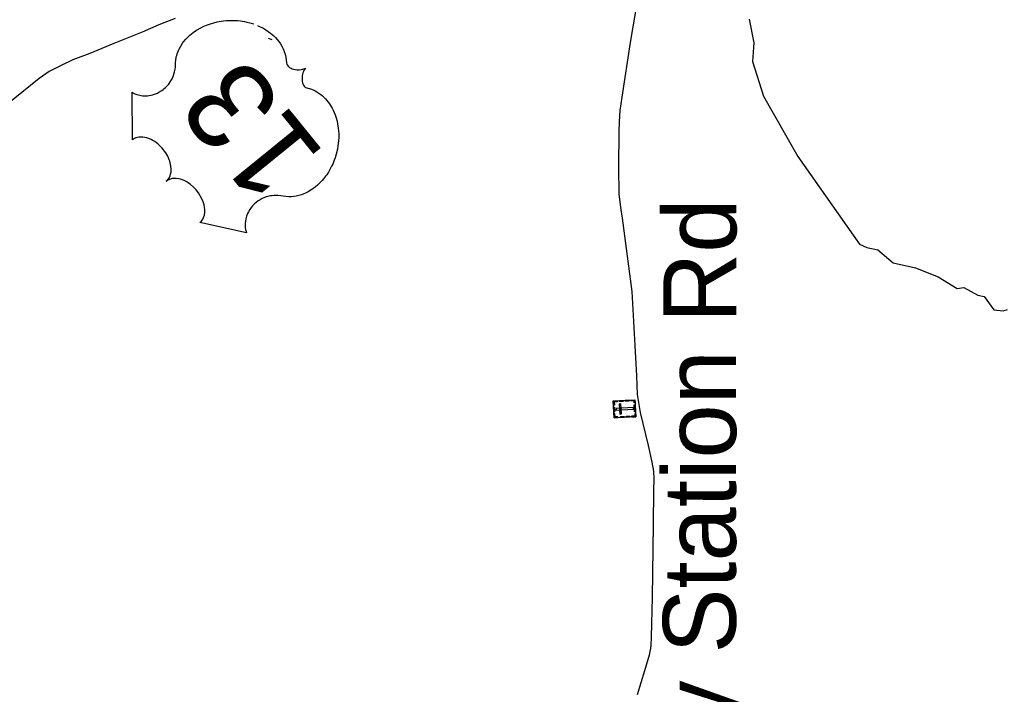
# Model space of a CAD drawing. Extents: x 2596159 to 2598075, y 851667 to 853493.
# Drawn here: x 2597062 to 2597143.5, y 851821.9 to 851877.7 of the extents above; entities that cross this region are included whole.
import ezdxf

# ---------------------------------------------------------------- set-up
doc = ezdxf.new("R2010")
doc.units = 0
doc.layers.add('Old_Level_1', color=7, linetype='Continuous')

msp = doc.modelspace()

# ---------------------------------------------------------------- linework, layer by layer
at = {"layer": 'Old_Level_1'}
for p, q in [((2597113.161, 851879.683), (2597112.506, 851875.786)), ((2597074.892, 851877.79), (2597073.528, 851877.271)), ((2597077.71, 851877.321), (2597078.071, 851877.433)), ((2597078.071, 851877.433), (2597078.348, 851877.497)), ((2597078.348, 851877.497), (2597078.682, 851877.56)), ((2597078.682, 851877.56), (2597078.892, 851877.588)), ((2597078.892, 851877.588), (2597079.123, 851877.609)), ((2597079.123, 851877.609), (2597079.397, 851877.623)), ((2597079.397, 851877.623), (2597079.7, 851877.626)), ((2597079.7, 851877.626), (2597080.038, 851877.607)), ((2597080.038, 851877.607), (2597080.296, 851877.58)), ((2597080.296, 851877.58), (2597080.614, 851877.529)), ((2597080.614, 851877.529), (2597080.799, 851877.492)), ((2597080.799, 851877.492), (2597081.052, 851877.43)), ((2597081.052, 851877.43), (2597081.378, 851877.329)), ((2597122.358, 851877.74), (2597122.735, 851875.782)), ((2597072.159, 851876.651), (2597069.818, 851875.72)), ((2597073.528, 851877.271), (2597072.159, 851876.651)), ((2597076.091, 851876.395), (2597076.367, 851876.62)), ((2597076.367, 851876.62), (2597076.647, 851876.813)), ((2597076.647, 851876.813), (2597076.994, 851877.013)), ((2597076.994, 851877.013), (2597077.211, 851877.121)), ((2597077.211, 851877.121), (2597077.475, 851877.231)), ((2597077.475, 851877.231), (2597077.71, 851877.321)), ((2597081.68, 851877.214), (2597081.925, 851877.106)), ((2597081.925, 851877.106), (2597082.129, 851876.999)), ((2597082.129, 851876.999), (2597082.382, 851876.853)), ((2597082.382, 851876.853), (2597082.766, 851876.579)), ((2597075.495, 851875.731), (2597075.577, 851875.844)), ((2597075.577, 851875.844), (2597075.775, 851876.079)), ((2597075.775, 851876.079), (2597075.877, 851876.19)), ((2597075.877, 851876.19), (2597076.091, 851876.395)), ((2597082.579, 851876.169), (2597082.881, 851876.053)), ((2597082.766, 851876.579), (2597082.897, 851876.472)), ((2597082.897, 851876.472), (2597083.044, 851876.338)), ((2597083.044, 851876.338), (2597083.174, 851876.207)), ((2597083.174, 851876.207), (2597083.295, 851876.076)), ((2597083.295, 851876.076), (2597083.446, 851875.889)), ((2597083.446, 851875.889), (2597083.583, 851875.693)), ((2597069.818, 851875.72), (2597067.831, 851874.886)), ((2597075.052, 851874.867), (2597075.101, 851875)), ((2597075.101, 851875), (2597075.157, 851875.139)), ((2597075.157, 851875.139), (2597075.209, 851875.257)), ((2597075.209, 851875.257), (2597075.346, 851875.507)), ((2597075.346, 851875.507), (2597075.495, 851875.731)), ((2597083.583, 851875.693), (2597083.7, 851875.497)), ((2597083.7, 851875.497), (2597083.809, 851875.284)), ((2597083.809, 851875.284), (2597083.908, 851875.047)), ((2597083.908, 851875.047), (2597083.981, 851874.819)), ((2597112.506, 851875.786), (2597111.828, 851871.278)), ((2597122.735, 851875.782), (2597122.635, 851874.218)), ((2597066.412, 851874.357), (2597065.464, 851873.898)), ((2597067.831, 851874.886), (2597066.412, 851874.357)), ((2597074.908, 851874.146), (2597074.926, 851874.312)), ((2597074.926, 851874.312), (2597074.978, 851874.603)), ((2597074.978, 851874.603), (2597075.01, 851874.731)), ((2597075.01, 851874.731), (2597075.052, 851874.867)), ((2597083.981, 851874.819), (2597084.037, 851874.574)), ((2597084.037, 851874.574), (2597084.091, 851874.126)), ((2597122.635, 851874.218), (2597123.527, 851871.357)), ((2597064.471, 851873.392), (2597063.636, 851872.809)), ((2597065.464, 851873.898), (2597064.471, 851873.392)), ((2597074.742, 851873.069), (2597074.84, 851873.382)), ((2597074.84, 851873.382), (2597074.877, 851873.579)), ((2597074.877, 851873.579), (2597074.898, 851873.76)), ((2597074.898, 851873.76), (2597074.903, 851874.009)), ((2597074.903, 851874.009), (2597074.908, 851874.146)), ((2597084.091, 851874.126), (2597084.115, 851874.004)), ((2597084.115, 851874.004), (2597084.141, 851873.946)), ((2597084.141, 851873.946), (2597084.229, 851873.827)), ((2597084.229, 851873.827), (2597084.338, 851873.738)), ((2597084.338, 851873.738), (2597084.472, 851873.663)), ((2597084.472, 851873.663), (2597084.561, 851873.626)), ((2597084.561, 851873.626), (2597084.691, 851873.585)), ((2597084.691, 851873.585), (2597084.8, 851873.56)), ((2597084.8, 851873.56), (2597084.944, 851873.542)), ((2597084.944, 851873.542), (2597085.055, 851873.538)), ((2597085.055, 851873.538), (2597085.141, 851873.536)), ((2597085.141, 851873.536), (2597085.34, 851873.56)), ((2597085.34, 851873.56), (2597085.426, 851873.581)), ((2597085.426, 851873.581), (2597085.532, 851873.615)), ((2597085.49, 851873.401), (2597085.447, 851873.281)), ((2597085.553, 851873.525), (2597085.49, 851873.401)), ((2597085.532, 851873.615), (2597085.672, 851873.684)), ((2597085.672, 851873.684), (2597085.553, 851873.525)), ((2597063.636, 851872.809), (2597057.987, 851868.27)), ((2597074.439, 851872.484), (2597074.537, 851872.634)), ((2597074.537, 851872.634), (2597074.623, 851872.791)), ((2597074.623, 851872.791), (2597074.742, 851873.069)), ((2597085.386, 851873.006), (2597085.375, 851872.872)), ((2597085.375, 851872.872), (2597085.375, 851872.722)), ((2597085.375, 851872.722), (2597085.395, 851872.579)), ((2597085.415, 851873.167), (2597085.386, 851873.006)), ((2597085.395, 851872.579), (2597085.418, 851872.47)), ((2597085.447, 851873.281), (2597085.415, 851873.167)), ((2597073.539, 851871.677), (2597073.775, 851871.823)), ((2597073.775, 851871.823), (2597073.882, 851871.898)), ((2597073.882, 851871.898), (2597073.983, 851871.98)), ((2597073.983, 851871.98), (2597074.084, 851872.071)), ((2597074.084, 851872.071), (2597074.178, 851872.164)), ((2597074.178, 851872.164), (2597074.269, 851872.268)), ((2597074.269, 851872.268), (2597074.348, 851872.361)), ((2597074.348, 851872.361), (2597074.439, 851872.484)), ((2597085.418, 851872.47), (2597085.449, 851872.378)), ((2597085.449, 851872.378), (2597085.498, 851872.274)), ((2597085.498, 851872.274), (2597085.549, 851872.199)), ((2597085.549, 851872.199), (2597085.598, 851872.142)), ((2597085.598, 851872.142), (2597085.681, 851872.077)), ((2597085.681, 851872.077), (2597085.847, 851872.033)), ((2597085.847, 851872.033), (2597086, 851871.988)), ((2597086, 851871.988), (2597086.16, 851871.932)), ((2597086.16, 851871.932), (2597086.339, 851871.857)), ((2597086.339, 851871.857), (2597086.463, 851871.796)), ((2597086.463, 851871.796), (2597086.603, 851871.717)), ((2597086.603, 851871.717), (2597086.758, 851871.618)), ((2597071.36, 851867.738), (2597071.321, 851871.677)), ((2597071.321, 851871.677), (2597071.389, 851871.638)), ((2597071.389, 851871.638), (2597071.558, 851871.56)), ((2597071.558, 851871.56), (2597071.702, 851871.506)), ((2597071.702, 851871.506), (2597071.952, 851871.436)), ((2597071.952, 851871.436), (2597072.073, 851871.417)), ((2597072.073, 851871.417), (2597072.197, 851871.4)), ((2597072.197, 851871.4), (2597072.32, 851871.393)), ((2597072.32, 851871.393), (2597072.433, 851871.39)), ((2597072.433, 851871.39), (2597072.585, 851871.398)), ((2597072.585, 851871.398), (2597072.732, 851871.414)), ((2597072.732, 851871.414), (2597072.887, 851871.44)), ((2597072.887, 851871.44), (2597073.015, 851871.47)), ((2597073.015, 851871.47), (2597073.267, 851871.553)), ((2597073.267, 851871.553), (2597073.417, 851871.616)), ((2597073.417, 851871.616), (2597073.539, 851871.677)), ((2597086.758, 851871.618), (2597086.916, 851871.503)), ((2597086.916, 851871.503), (2597087.068, 851871.376)), ((2597087.068, 851871.376), (2597087.197, 851871.26)), ((2597087.197, 851871.26), (2597087.326, 851871.128)), ((2597087.326, 851871.128), (2597087.434, 851871.003)), ((2597087.434, 851871.003), (2597087.542, 851870.867)), ((2597111.828, 851871.278), (2597111.662, 851870.173)), ((2597123.527, 851871.357), (2597126.377, 851866.381)), ((2597087.542, 851870.867), (2597087.634, 851870.734)), ((2597087.634, 851870.734), (2597087.74, 851870.578)), ((2597087.74, 851870.578), (2597087.86, 851870.375)), ((2597087.86, 851870.375), (2597087.948, 851870.198)), ((2597087.948, 851870.198), (2597088.034, 851870.006)), ((2597111.662, 851870.173), (2597111.591, 851869.24)), ((2597088.034, 851870.006), (2597088.115, 851869.802)), ((2597088.115, 851869.802), (2597088.19, 851869.574)), ((2597088.19, 851869.574), (2597088.272, 851869.28)), ((2597088.272, 851869.28), (2597088.317, 851869.065)), ((2597088.317, 851869.065), (2597088.374, 851868.715)), ((2597088.374, 851868.715), (2597088.407, 851868.279)), ((2597111.591, 851869.24), (2597111.576, 851868.429)), ((2597071.433, 851867.793), (2597071.36, 851867.738)), ((2597071.525, 851867.85), (2597071.433, 851867.793)), ((2597071.64, 851867.905), (2597071.525, 851867.85)), ((2597071.762, 851867.94), (2597071.64, 851867.905)), ((2597071.881, 851867.969), (2597071.762, 851867.94)), ((2597072.012, 851867.979), (2597071.881, 851867.969)), ((2597072.206, 851867.973), (2597072.012, 851867.979)), ((2597072.387, 851867.947), (2597072.206, 851867.973)), ((2597072.529, 851867.917), (2597072.387, 851867.947)), ((2597072.702, 851867.857), (2597072.529, 851867.917)), ((2597072.9, 851867.772), (2597072.702, 851867.857)), ((2597073.042, 851867.698), (2597072.9, 851867.772)), ((2597073.195, 851867.606), (2597073.042, 851867.698)), ((2597088.394, 851867.66), (2597088.347, 851867.244)), ((2597088.408, 851867.928), (2597088.394, 851867.66)), ((2597088.407, 851868.279), (2597088.408, 851867.928)), ((2597111.576, 851868.429), (2597111.555, 851865.48)), ((2597073.35, 851867.493), (2597073.195, 851867.606)), ((2597073.462, 851867.404), (2597073.35, 851867.493)), ((2597073.595, 851867.287), (2597073.462, 851867.404)), ((2597073.709, 851867.175), (2597073.595, 851867.287)), ((2597073.814, 851867.061), (2597073.709, 851867.175)), ((2597073.921, 851866.932), (2597073.814, 851867.061)), ((2597074.004, 851866.824), (2597073.921, 851866.932)), ((2597088.304, 851866.988), (2597088.203, 851866.558)), ((2597088.347, 851867.244), (2597088.304, 851866.988)), ((2597074.1, 851866.686), (2597074.004, 851866.824)), ((2597074.185, 851866.544), (2597074.1, 851866.686)), ((2597074.264, 851866.402), (2597074.185, 851866.544)), ((2597074.337, 851866.253), (2597074.264, 851866.402)), ((2597074.399, 851866.101), (2597074.337, 851866.253)), ((2597074.443, 851865.978), (2597074.399, 851866.101)), ((2597088.042, 851866.06), (2597087.914, 851865.745)), ((2597088.116, 851866.264), (2597088.042, 851866.06)), ((2597088.203, 851866.558), (2597088.116, 851866.264)), ((2597126.377, 851866.381), (2597131.469, 851859.124)), ((2597074.478, 851865.851), (2597074.443, 851865.978)), ((2597074.536, 851865.583), (2597074.478, 851865.851)), ((2597074.556, 851865.33), (2597074.536, 851865.583)), ((2597074.548, 851865.112), (2597074.556, 851865.229)), ((2597074.556, 851865.229), (2597074.556, 851865.33)), ((2597087.687, 851865.294), (2597087.551, 851865.065)), ((2597087.825, 851865.557), (2597087.687, 851865.294)), ((2597087.914, 851865.745), (2597087.825, 851865.557)), ((2597111.555, 851865.48), (2597111.585, 851863.281)), ((2597074.143, 851864.318), (2597074.248, 851864.417)), ((2597074.284, 851864.416), (2597074.143, 851864.318)), ((2597074.248, 851864.417), (2597074.308, 851864.484)), ((2597074.359, 851864.453), (2597074.284, 851864.416)), ((2597074.308, 851864.484), (2597074.361, 851864.558)), ((2597074.544, 851864.52), (2597074.359, 851864.453)), ((2597074.361, 851864.558), (2597074.41, 851864.645)), ((2597074.41, 851864.645), (2597074.47, 851864.778)), ((2597074.47, 851864.778), (2597074.509, 851864.904)), ((2597074.509, 851864.904), (2597074.548, 851865.112)), ((2597074.641, 851864.539), (2597074.544, 851864.52)), ((2597074.746, 851864.554), (2597074.641, 851864.539)), ((2597074.954, 851864.555), (2597074.746, 851864.554)), ((2597075.179, 851864.527), (2597074.954, 851864.555)), ((2597075.317, 851864.49), (2597075.179, 851864.527)), ((2597075.483, 851864.435), (2597075.317, 851864.49)), ((2597075.676, 851864.354), (2597075.483, 851864.435)), ((2597087.156, 851864.518), (2597087.033, 851864.372)), ((2597087.324, 851864.73), (2597087.156, 851864.518)), ((2597087.416, 851864.857), (2597087.324, 851864.73)), ((2597087.551, 851865.065), (2597087.416, 851864.857)), ((2597075.835, 851864.268), (2597075.676, 851864.354)), ((2597075.996, 851864.167), (2597075.835, 851864.268)), ((2597076.131, 851864.068), (2597075.996, 851864.167)), ((2597076.404, 851863.839), (2597076.131, 851864.068)), ((2597076.622, 851863.609), (2597076.404, 851863.839)), ((2597076.802, 851863.378), (2597076.622, 851863.609)), ((2597086.098, 851863.577), (2597085.873, 851863.447)), ((2597086.301, 851863.711), (2597086.098, 851863.577)), ((2597086.466, 851863.837), (2597086.301, 851863.711)), ((2597086.657, 851863.998), (2597086.466, 851863.837)), ((2597086.856, 851864.183), (2597086.657, 851863.998)), ((2597087.033, 851864.372), (2597086.856, 851864.183)), ((2597076.964, 851863.127), (2597076.802, 851863.378)), ((2597077.093, 851862.882), (2597076.964, 851863.127)), ((2597077.201, 851862.628), (2597077.093, 851862.882)), ((2597081.909, 851862.796), (2597081.757, 851862.703)), ((2597082.078, 851862.886), (2597081.909, 851862.796)), ((2597082.213, 851862.95), (2597082.078, 851862.886)), ((2597082.419, 851863.026), (2597082.213, 851862.95)), ((2597082.559, 851863.067), (2597082.419, 851863.026)), ((2597082.758, 851863.108), (2597082.559, 851863.067)), ((2597082.898, 851863.13), (2597082.758, 851863.108)), ((2597083.06, 851863.147), (2597082.898, 851863.13)), ((2597083.245, 851863.153), (2597083.06, 851863.147)), ((2597083.385, 851863.148), (2597083.245, 851863.153)), ((2597083.633, 851863.119), (2597083.385, 851863.148)), ((2597083.823, 851863.08), (2597083.633, 851863.119)), ((2597084.048, 851863.052), (2597083.823, 851863.08)), ((2597084.28, 851863.037), (2597084.048, 851863.052)), ((2597084.476, 851863.042), (2597084.28, 851863.037)), ((2597084.694, 851863.062), (2597084.476, 851863.042)), ((2597084.887, 851863.093), (2597084.694, 851863.062)), ((2597085.109, 851863.143), (2597084.887, 851863.093)), ((2597085.329, 851863.21), (2597085.109, 851863.143)), ((2597085.52, 851863.281), (2597085.329, 851863.21)), ((2597085.671, 851863.346), (2597085.52, 851863.281)), ((2597085.873, 851863.447), (2597085.671, 851863.346)), ((2597111.585, 851863.281), (2597111.701, 851862.141)), ((2597077.274, 851862.38), (2597077.201, 851862.628)), ((2597077.318, 851862.145), (2597077.274, 851862.38)), ((2597077.334, 851861.999), (2597077.318, 851862.145)), ((2597077.333, 851861.761), (2597077.334, 851861.999)), ((2597081.051, 851861.989), (2597080.941, 851861.801)), ((2597081.159, 851862.139), (2597081.051, 851861.989)), ((2597081.292, 851862.299), (2597081.159, 851862.139)), ((2597081.443, 851862.452), (2597081.292, 851862.299)), ((2597081.581, 851862.571), (2597081.443, 851862.452)), ((2597081.757, 851862.703), (2597081.581, 851862.571)), ((2597111.701, 851862.141), (2597111.843, 851861.274)), ((2597077.121, 851861.107), (2597077.167, 851861.174)), ((2597077.167, 851861.174), (2597077.238, 851861.324)), ((2597077.238, 851861.324), (2597077.302, 851861.525)), ((2597077.302, 851861.525), (2597077.333, 851861.761)), ((2597080.725, 851861.214), (2597080.691, 851861.012)), ((2597080.787, 851861.434), (2597080.725, 851861.214)), ((2597080.87, 851861.653), (2597080.787, 851861.434)), ((2597080.941, 851861.801), (2597080.87, 851861.653)), ((2597111.843, 851861.274), (2597112.647, 851855.209)), ((2597076.929, 851860.901), (2597077.023, 851860.987)), ((2597080.777, 851860.058), (2597076.929, 851860.901)), ((2597077.023, 851860.987), (2597077.121, 851861.107)), ((2597080.691, 851861.012), (2597080.672, 851860.82)), ((2597080.672, 851860.82), (2597080.675, 851860.654)), ((2597080.675, 851860.654), (2597080.684, 851860.501)), ((2597080.684, 851860.501), (2597080.71, 851860.32)), ((2597080.71, 851860.32), (2597080.747, 851860.156)), ((2597080.747, 851860.156), (2597080.777, 851860.058)), ((2597131.469, 851859.124), (2597132.08, 851858.847)), ((2597132.08, 851858.847), (2597133.006, 851858.66)), ((2597133.006, 851858.66), (2597134.266, 851857.585)), ((2597134.266, 851857.585), (2597136.111, 851857.15)), ((2597136.111, 851857.15), (2597137.984, 851856.408)), ((2597137.984, 851856.408), (2597139.561, 851855.464)), ((2597139.561, 851855.464), (2597140.106, 851855.545)), ((2597140.106, 851855.545), (2597141.26, 851854.902)), ((2597112.647, 851855.209), (2597112.911, 851850.729)), ((2597141.26, 851854.902), (2597141.779, 851854.796)), ((2597141.779, 851854.796), (2597142.578, 851853.678)), ((2597142.578, 851853.678), (2597143.362, 851853.597)), ((2597143.362, 851853.597), (2597143.709, 851853.713)), ((2597112.911, 851850.729), (2597113.031, 851848.244)), ((2597113.031, 851848.244), (2597113.095, 851846.697)), ((2597113.095, 851846.697), (2597113.328, 851845.201)), ((2597113.328, 851845.201), (2597113.987, 851842.479)), ((2597113.987, 851842.479), (2597114.309, 851841.086)), ((2597114.309, 851841.086), (2597114.454, 851840.345)), ((2597114.454, 851840.345), (2597114.461, 851839.673)), ((2597114.461, 851839.673), (2597114.452, 851838.787)), ((2597114.452, 851838.787), (2597114.403, 851835.924)), ((2597114.403, 851835.924), (2597114.319, 851829.909)), ((2597114.319, 851829.909), (2597114.258, 851826.636)), ((2597114.258, 851826.636), (2597114.216, 851825.872)), ((2597114.216, 851825.872), (2597114.086, 851825.12)), ((2597114.086, 851825.12), (2597113.706, 851823.821)), ((2597113.706, 851823.821), (2597113.092, 851821.837))]:
    msp.add_line(p, q, dxfattribs=at)
for points in [[(2597111.19, 851844.756), (2597111.119, 851846.157), (2597112.911, 851846.248), (2597112.982, 851844.847)], [(2597111.424, 851846.173), (2597111.428, 851846.093), (2597111.202, 851846.082), (2597111.216, 851845.796), (2597111.138, 851845.792), (2597111.12, 851846.158)], [(2597111.654, 851845.067), (2597111.786, 851845.074), (2597111.744, 851845.903), (2597111.613, 851845.896)], [(2597111.943, 851846.119), (2597111.638, 851846.103), (2597111.634, 851846.184), (2597111.939, 851846.199)], [(2597112.407, 851846.142), (2597112.102, 851846.127), (2597112.098, 851846.207), (2597112.403, 851846.222)], [(2597112.923, 851846.014), (2597112.842, 851846.01), (2597112.834, 851846.165), (2597112.55, 851846.151), (2597112.546, 851846.229), (2597112.911, 851846.248)], [(2597112.881, 851845.247), (2597112.851, 851845.844), (2597112.931, 851845.848), (2597112.961, 851845.251)], [(2597111.164, 851845.277), (2597111.145, 851845.642), (2597111.226, 851845.646), (2597111.244, 851845.281)], [(2597111.495, 851844.771), (2597111.491, 851844.851), (2597111.264, 851844.84), (2597111.25, 851845.125), (2597111.172, 851845.121), (2597111.19, 851844.756)], [(2597111.357, 851845.534), (2597111.364, 851845.402), (2597112.791, 851845.474), (2597112.785, 851845.606)], [(2597112.017, 851844.798), (2597111.712, 851844.782), (2597111.708, 851844.862), (2597112.013, 851844.878)], [(2597112.49, 851844.821), (2597112.185, 851844.806), (2597112.181, 851844.886), (2597112.486, 851844.902)], [(2597112.97, 851845.079), (2597112.889, 851845.075), (2597112.897, 851844.92), (2597112.613, 851844.906), (2597112.616, 851844.828), (2597112.982, 851844.846)]]:
    msp.add_lwpolyline(points, close=True, dxfattribs=at)

# ---------------------------------------------------------------- texts
for s, height, rotation, p in [('13', 7.2779, 129.10289, (2597087.392, 851866.503)), ('Early Station Rd', 6.0253, 89.92248, (2597121.216, 851804.669))]:
    msp.add_text(s, height=height, rotation=rotation, dxfattribs=at).set_placement(p)

doc.saveas('drawing.dxf')
